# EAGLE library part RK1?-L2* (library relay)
1.5 GHz MICROWAVE RELAY NAiS Source: http://www.mew-europe.com/.. en_ds_61311_0000.pdf
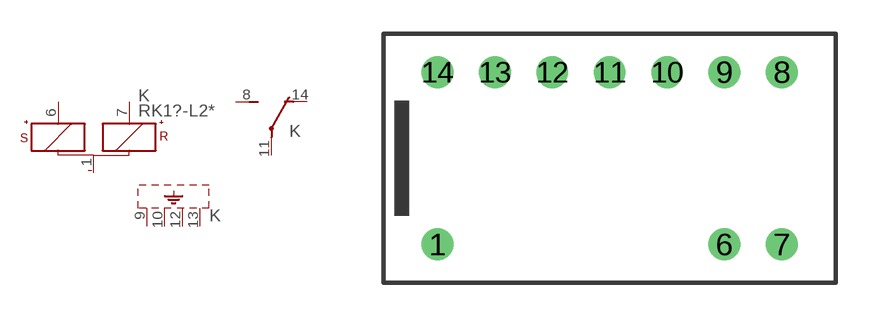
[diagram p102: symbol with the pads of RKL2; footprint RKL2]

Designator prefix K; gates 1=+KS+KR- 2=U S1=SHIELD-4

## RK1-L2 (MF: AROMAT/ MATSUSHITA; MPN: RK1-L2-12V; OC_FARNELL: 1616207; OC_NEWARK: 10C9189)  [RKL2]
1  1:-  pas
6  1:S+  pas
7  1:R+  pas
8  2:S  pas
9  S1:SH  pas
10  S1:SH  pas
11  2:P  pas
12  S1:SH  pas
13  S1:SH  pas
14  2:O  pas

## RK1R-L2 (OC_FARNELL: unknown; OC_NEWARK: unknown)  [RKL2]
1  1:-  pas
6  1:S+  pas
7  1:R+  pas
8  2:O  pas
9  S1:SH  pas
10  S1:SH  pas
11  2:P  pas
12  S1:SH  pas
13  S1:SH  pas
14  2:S  pas

## Footprint RKL2 (pad centres in mm)
1.5 GHz MICROWAVE RELAY NAiS Source: http://www.mew-europe.com/.. en_ds_61311_0000.pdf
drill 0.9 round: 1 -7.62,-3.81; 6 5.08,-3.81; 7 7.62,-3.81; 8 7.62,3.81; 9 5.08,3.81; 10 2.54,3.81; 11 0,3.81; 12 -2.54,3.81; 13 -5.08,3.81; 14 -7.62,3.81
